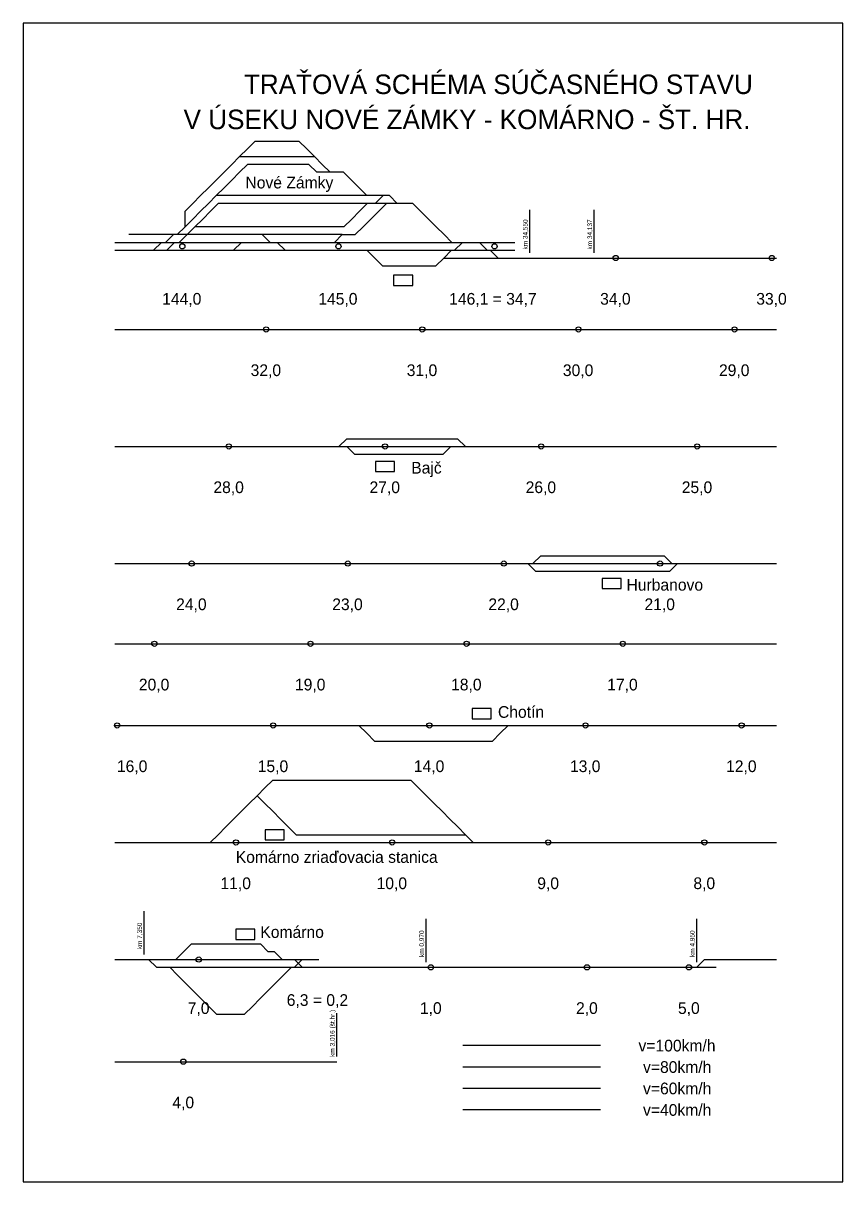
# Model space of a CAD drawing. Extents: x 44 to 1904, y 374 to 671.
# Drawn here: x 1693.9 to 1903.9, y 373.6 to 670.6 of the extents above; entities that cross this region are included whole.
import ezdxf

# ---------------------------------------------------------------- set-up
doc = ezdxf.new("R2010")
doc.units = 0
for name, color, linetype in [('2', 7, 'Continuous'), ('NAVRH', 7, 'Continuous'), ('Vrstva 1', 7, 'Continuous')]:
    doc.layers.add(name, color=color, linetype=linetype)

msp = doc.modelspace()

# ---------------------------------------------------------------- linework, layer by layer
at = {"layer": '2'}
for p, q in [((1753.39, 640.39), (1764.57, 640.39)), ((1749.39, 636.39), (1768.57, 636.39)), ((1767.12, 634.39), (1751.39, 634.39)), ((1776.01, 632.39), (1769.12, 632.39)), ((1782.01, 626.39), (1743.39, 626.39)), ((1782.09, 624.39), (1743.92, 624.39)), ((1787.76, 626.39), (1782.01, 626.39)), ((1787.01, 624.39), (1782.09, 624.39)), ((1793.76, 624.39), (1787.01, 624.39)), ((1735.39, 618.39), (1735.39, 622.39)), ((1776.09, 618.39), (1737.92, 618.39)), ((1775.65, 616.39), (1720.98, 616.39)), ((1775.65, 616.39), (1779.01, 616.39)), ((1717.41, 614.39), (1819.89, 614.39)), ((1717.41, 612.39), (1819.89, 612.39)), ((1801.69, 610.39), (1823.73, 610.39)), ((1823.73, 610.39), (1840.25, 610.39)), ((1840.25, 610.39), (1886.95, 610.39)), ((1786.01, 608.39), (1799.69, 608.39)), ((1717.41, 592.09), (1886.95, 592.09)), ((1717.41, 562.09), (1757.86, 562.09)), ((1757.86, 562.09), (1886.95, 562.09)), ((1776.83, 564.09), (1805.23, 564.09)), ((1778.85, 560.09), (1801.51, 560.09)), ((1717.41, 532.09), (1886.95, 532.09)), ((1826.53, 534.09), (1858.13, 534.09)), ((1825.21, 530.09), (1859.57, 530.09)), ((1717.41, 511.52), (1798.31, 511.52)), ((1798.31, 511.52), (1886.95, 511.52)), ((1717.41, 490.58), (1886.95, 490.58)), ((1783.96, 486.58), (1814.16, 486.58)), ((1757.85, 476.58), (1793.25, 476.58)), ((1717.41, 460.58), (1838.77, 460.58)), ((1763.85, 462.58), (1807.25, 462.58)), ((1838.77, 460.58), (1886.95, 460.58)), ((1717.41, 430.58), (1724.9, 430.58)), ((1724.9, 430.58), (1763.42, 430.58)), ((1765.42, 428.58), (1797.18, 428.58)), ((1797.18, 428.58), (1866.5, 428.58)), ((1868.5, 430.58), (1886.95, 430.58)), ((1717.41, 404.39), (1774.32, 404.39))]:
    msp.add_line(p, q, dxfattribs=at)
at = {"layer": 'NAVRH'}
for p, q in [((1751.39, 638.39), (1753.39, 640.39)), ((1766.57, 638.39), (1764.57, 640.39)), ((1747.39, 634.39), (1749.39, 636.39)), ((1749.39, 636.39), (1751.39, 638.39)), ((1768.57, 636.39), (1766.57, 638.39)), ((1770.57, 634.39), (1768.57, 636.39)), ((1745.39, 632.39), (1747.39, 634.39)), ((1749.39, 632.39), (1751.39, 634.39)), ((1769.12, 632.39), (1767.12, 634.39)), ((1772.57, 632.39), (1770.57, 634.39)), ((1741.39, 628.39), (1743.39, 630.39)), ((1743.39, 630.39), (1745.39, 632.39)), ((1745.39, 628.39), (1747.39, 630.39)), ((1747.39, 630.39), (1749.39, 632.39)), ((1778.01, 630.39), (1776.01, 632.39)), ((1780.01, 628.39), (1778.01, 630.39)), ((1739.39, 626.39), (1741.39, 628.39)), ((1739.39, 626.39), (1741.39, 628.39)), ((1743.39, 626.39), (1745.39, 628.39)), ((1782.01, 626.39), (1780.01, 628.39)), ((1735.39, 622.39), (1737.39, 624.39)), ((1737.39, 624.39), (1739.39, 626.39)), ((1739.39, 622.39), (1741.39, 624.39)), ((1741.39, 624.39), (1743.39, 626.39)), ((1741.92, 622.39), (1743.92, 624.39)), ((1780.09, 622.39), (1782.09, 624.39)), ((1784.13, 624.39), (1786.13, 626.39)), ((1785.01, 622.39), (1787.01, 624.39)), ((1789.76, 624.39), (1787.76, 626.39)), ((1795.76, 622.39), (1793.76, 624.39)), ((1737.39, 620.39), (1739.39, 622.39)), ((1739.92, 620.39), (1741.92, 622.39)), ((1778.09, 620.39), (1780.09, 622.39)), ((1783.01, 620.39), (1785.01, 622.39)), ((1797.76, 620.39), (1795.76, 622.39)), ((1733.39, 616.39), (1735.39, 618.39)), ((1735.39, 618.39), (1737.39, 620.39)), ((1735.92, 616.39), (1737.92, 618.39)), ((1737.92, 618.39), (1739.92, 620.39)), ((1776.09, 618.39), (1778.09, 620.39)), ((1779.01, 616.39), (1781.01, 618.39)), ((1781.01, 618.39), (1783.01, 620.39)), ((1799.76, 618.39), (1797.76, 620.39)), ((1801.76, 616.39), (1799.76, 618.39)), ((1730.4, 614.39), (1732.4, 616.39)), ((1733.92, 614.39), (1735.92, 616.39)), ((1757.17, 614.39), (1755.17, 616.39)), ((1773.65, 614.39), (1775.65, 616.39)), ((1803.76, 614.39), (1801.76, 616.39)), ((1727.33, 612.39), (1729.33, 614.39)), ((1730.69, 612.39), (1732.69, 614.39)), ((1747.85, 612.39), (1749.85, 614.39)), ((1761.01, 612.39), (1759.01, 614.39)), ((1784.01, 610.39), (1782.01, 612.39)), ((1801.69, 610.39), (1803.69, 612.39)), ((1804.45, 612.39), (1806.45, 614.39)), ((1812.81, 612.39), (1810.81, 614.39)), ((1815.6, 610.39), (1813.6, 612.39)), ((1786.01, 608.39), (1784.01, 610.39)), ((1799.69, 608.39), (1801.69, 610.39)), ((1774.83, 562.09), (1776.83, 564.09)), ((1778.85, 560.09), (1776.85, 562.09)), ((1801.51, 560.09), (1803.51, 562.09)), ((1807.23, 562.09), (1805.23, 564.09)), ((1825.21, 530.09), (1823.21, 532.09)), ((1824.53, 532.09), (1826.53, 534.09)), ((1860.13, 532.09), (1858.13, 534.09)), ((1859.57, 530.09), (1861.57, 532.09)), ((1781.96, 488.58), (1779.96, 490.58)), ((1816.16, 488.58), (1818.16, 490.58)), ((1783.96, 486.58), (1781.96, 488.58)), ((1814.16, 486.58), (1816.16, 488.58)), ((1755.85, 474.58), (1757.85, 476.58)), ((1795.25, 474.58), (1793.25, 476.58)), ((1751.85, 470.58), (1753.85, 472.58)), ((1753.85, 472.58), (1755.85, 474.58)), ((1755.85, 470.58), (1753.85, 472.58)), ((1797.25, 472.58), (1795.25, 474.58)), ((1799.25, 470.58), (1797.25, 472.58)), ((1749.85, 468.58), (1751.85, 470.58)), ((1757.85, 468.58), (1755.85, 470.58)), ((1801.25, 468.58), (1799.25, 470.58)), ((1745.85, 464.58), (1747.85, 466.58)), ((1747.85, 466.58), (1749.85, 468.58)), ((1759.85, 466.58), (1757.85, 468.58)), ((1763.85, 462.58), (1759.85, 466.58)), ((1803.25, 466.58), (1801.25, 468.58)), ((1805.25, 464.58), (1803.25, 466.58)), ((1743.85, 462.58), (1745.85, 464.58)), ((1807.25, 462.58), (1805.25, 464.58)), ((1741.85, 460.58), (1743.85, 462.58)), ((1809.25, 460.58), (1807.25, 462.58)), ((1735.03, 432.58), (1737.03, 434.58)), ((1756.73, 432.58), (1754.73, 434.58)), ((1733.03, 430.58), (1735.03, 432.58)), ((1760.3, 430.58), (1758.3, 432.58)), ((1728.06, 428.58), (1726.06, 430.58)), ((1733.46, 426.58), (1731.46, 428.58)), ((1760.64, 426.58), (1762.64, 428.58)), ((1765.42, 428.58), (1763.42, 430.58)), ((1763.42, 428.58), (1765.42, 430.58)), ((1866.5, 428.58), (1868.5, 430.58)), ((1735.46, 424.58), (1733.46, 426.58)), ((1758.64, 424.58), (1760.64, 426.58)), ((1737.46, 422.58), (1735.46, 424.58)), ((1739.46, 420.58), (1737.46, 422.58)), ((1754.64, 420.58), (1756.64, 422.58)), ((1756.64, 422.58), (1758.64, 424.58)), ((1741.46, 418.58), (1739.46, 420.58)), ((1752.64, 418.58), (1754.64, 420.58)), ((1743.46, 416.58), (1741.46, 418.58)), ((1750.64, 416.58), (1752.64, 418.58))]:
    msp.add_line(p, q, dxfattribs=at)
for points in [[(1788.82, 603.39), (1793.72, 603.39), (1793.72, 605.99), (1788.82, 605.99)], [(1784.19, 555.65), (1789.09, 555.65), (1789.09, 558.25), (1784.19, 558.25)], [(1842.23, 525.65), (1847.12, 525.65), (1847.12, 528.25), (1842.23, 528.25)], [(1808.97, 492.31), (1813.87, 492.31), (1813.87, 494.91), (1808.97, 494.91)], [(1755.93, 461.25), (1760.82, 461.25), (1760.82, 463.85), (1755.93, 463.85)], [(1748.37, 435.73), (1753.26, 435.73), (1753.26, 438.33), (1748.37, 438.33)]]:
    msp.add_lwpolyline(points, close=True, dxfattribs=at)
for centre in [(1734.69, 613.39), (1774.69, 613.39), (1814.69, 613.39), (1845.73, 610.39), (1885.73, 610.39), (1756.18, 592.09), (1796.18, 592.09), (1836.18, 592.09), (1876.18, 592.09), (1746.63, 562.09), (1786.63, 562.09), (1826.63, 562.09), (1866.63, 562.09), (1737.09, 532.09), (1777.09, 532.09), (1817.09, 532.09), (1857.09, 532.09), (1727.54, 511.52), (1767.54, 511.52), (1807.54, 511.52), (1847.54, 511.52), (1718, 490.58), (1758, 490.58), (1798, 490.58), (1838, 490.58), (1878, 490.58), (1748.45, 460.58), (1788.45, 460.58), (1828.45, 460.58), (1868.45, 460.58), (1738.9, 430.58), (1798.38, 428.58), (1838.38, 428.58), (1864.5, 428.58), (1734.96, 404.39)]:
    msp.add_circle(centre, 0.666, dxfattribs=at)
at = {"layer": 'Vrstva 1'}
for p, q in [((1823.73, 611.71), (1823.73, 622.79)), ((1840.25, 611.71), (1840.25, 622.79)), ((1724.9, 431.9), (1724.9, 442.98)), ((1797.18, 429.9), (1797.18, 440.98)), ((1866.5, 429.9), (1866.5, 440.98)), ((1737.03, 434.58), (1754.73, 434.58)), ((1758.3, 432.58), (1756.73, 432.58)), ((1728.06, 428.58), (1765.42, 428.58)), ((1763.42, 430.58), (1769.68, 430.58)), ((1866.5, 428.58), (1871.51, 428.58)), ((1743.46, 416.58), (1750.64, 416.58)), ((1774.29, 405.71), (1774.29, 416.79)), ((1841.84, 408.52), (1806.59, 408.52)), ((1841.84, 403.02), (1806.59, 403.02)), ((1841.84, 397.53), (1806.59, 397.53)), ((1841.84, 392.03), (1806.59, 392.03))]:
    msp.add_line(p, q, dxfattribs=at)
msp.add_lwpolyline([(1693.93, 670.6), (1693.93, 373.6), (1903.93, 373.6), (1903.93, 670.6)], close=True, dxfattribs=at)

# ---------------------------------------------------------------- texts
at = {"layer": 'NAVRH'}
for s, p in [('TRAŤOVÁ SCHÉMA SÚČASNÉHO STAVU ', (1750.48, 652.43)), ('V ÚSEKU NOVÉ ZÁMKY - KOMÁRNO - ŠT. HR. ', (1735.02, 643.43))]:
    msp.add_text(s, height=5, dxfattribs=at).set_placement(p)
for s, p in [('Nové Zámky', (1750.87, 628.24)), ('144,0', (1729.54, 598.44)), ('145,0', (1769.54, 598.44)), ('146,1 = 34,7', (1803.07, 598.44)), ('34,0', (1841.75, 598.44)), ('33,0', (1881.75, 598.44)), ('32,0', (1752.2, 580.14)), ('31,0', (1792.2, 580.14)), ('30,0', (1832.2, 580.14)), ('29,0', (1872.2, 580.14)), ('Bajč', (1793.35, 555.14)), ('28,0', (1742.66, 550.14)), ('27,0', (1782.66, 550.14)), ('26,0', (1822.66, 550.14)), ('25,0', (1862.66, 550.14)), ('Hurbanovo', (1848.5, 525.14)), ('24,0', (1733.11, 520.14)), ('23,0', (1773.11, 520.14)), ('22,0', (1813.11, 520.14)), ('21,0', (1853.11, 520.14)), ('20,0', (1723.56, 499.56)), ('19,0', (1763.56, 499.56)), ('18,0', (1803.56, 499.56)), ('17,0', (1843.56, 499.56)), ('Chotín', (1815.57, 492.54)), ('16,0', (1717.94, 478.63)), ('15,0', (1754.02, 478.63)), ('14,0', (1794.02, 478.63)), ('13,0', (1834.02, 478.63)), ('12,0', (1874.02, 478.63)), ('Komárno zriaďovacia stanica', (1748.39, 455.36)), ('11,0', (1744.47, 448.63)), ('10,0', (1784.47, 448.63)), ('9,0', (1825.64, 448.63)), ('8,0', (1865.64, 448.63)), ('Komárno', (1754.69, 436.13)), ('7,0', (1736.09, 416.63)), ('6,3 = 0,2', (1761.45, 418.69)), ('1,0', (1795.57, 416.63)), ('2,0', (1835.57, 416.63)), ('5,0', (1861.69, 416.63)), ('v=100km/h', (1851.58, 407.02)), ('v=80km/h', (1852.74, 401.52)), ('v=60km/h', (1852.74, 396.03)), ('4,0', (1732.15, 392.44)), ('v=40km/h', (1852.74, 390.53))]:
    msp.add_text(s, height=3, rotation=360, dxfattribs=at).set_placement(p)
at = {"layer": 'Vrstva 1'}
for s, p in [('km 34,550', (1823.17, 612.57)), ('km 34,137', (1839.69, 612.57)), ('km 7,350', (1724.35, 433.23)), ('km 0,970', (1796.63, 431.23)), ('km 4,950', (1865.95, 431.23)), ('km 3,016 (št.hr.)', (1773.74, 405.63))]:
    msp.add_text(s, height=1.2, rotation=90, dxfattribs=at).set_placement(p)

doc.saveas('drawing.dxf')
